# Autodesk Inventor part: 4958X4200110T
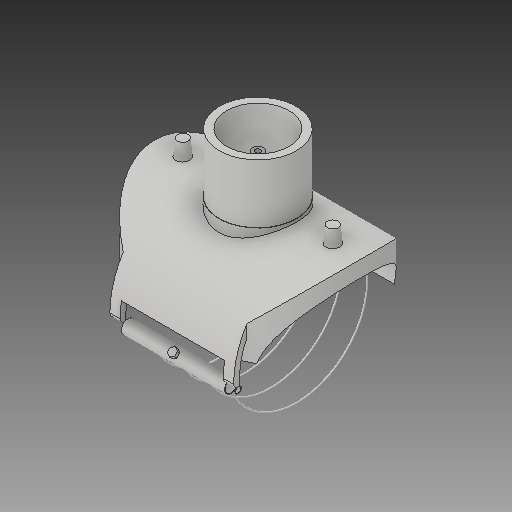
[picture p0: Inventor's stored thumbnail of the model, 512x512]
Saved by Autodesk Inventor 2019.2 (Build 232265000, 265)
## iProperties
Created: 2020-06
Part Number: 4958X4200110T
Material: Generic
Description: Plasson Branch Saddle 200x110
Document SubType Name: Modeling
Designer: KIM
Density: 1 g/cm^3
Appearance: Default
Author: KIM
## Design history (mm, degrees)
derived "4958X4.ipt"
feature "Solid1::4958X4.ipt"
tag "TaggingFeature1"
body "Solid1"
other parameters: "d0" = 295, "d3" = 246.2, "d4" = 111, "d7" = 89, "d9" = 84, "d10" = 0.5, "d11" = 1, "d12" = 27.75, "d13" = 16, "d14" = 8, "d16" = 10 deg, "d17" = 10 deg, "d19" = 0, "d23" = 0, "d26" = 0, "d27" = 177, "d28" = 0, "d29" = 147.5, "d30" = 0, "d31" = 1, "d32" = 1, "d33" = 19.2, "d34" = 9.6, "d35" = 45 deg, "d36" = 147.5, "d37" = 0, "d38" = 5, "d39" = 85 deg, "d40" = 27.75, "d41" = 16, "d42" = 107.27273, "d49" = 3, "d50" = 6, "d51" = 5, "d54" = 0, "d57" = 35 deg, "d60" = 18.4375, "d61" = 1, "d62" = 90 deg, "d63" = 2, "d64" = 0, "d65" = 0, "d68" = 36.875, "d70" = 0.57711, "d71" = 10 deg, "d73" = 8.085, "B" = 277, "L" = 295, "LS" = 84, "H1" = 111, "Dt" = 16, "di" = 89, "d72" = 23.1
